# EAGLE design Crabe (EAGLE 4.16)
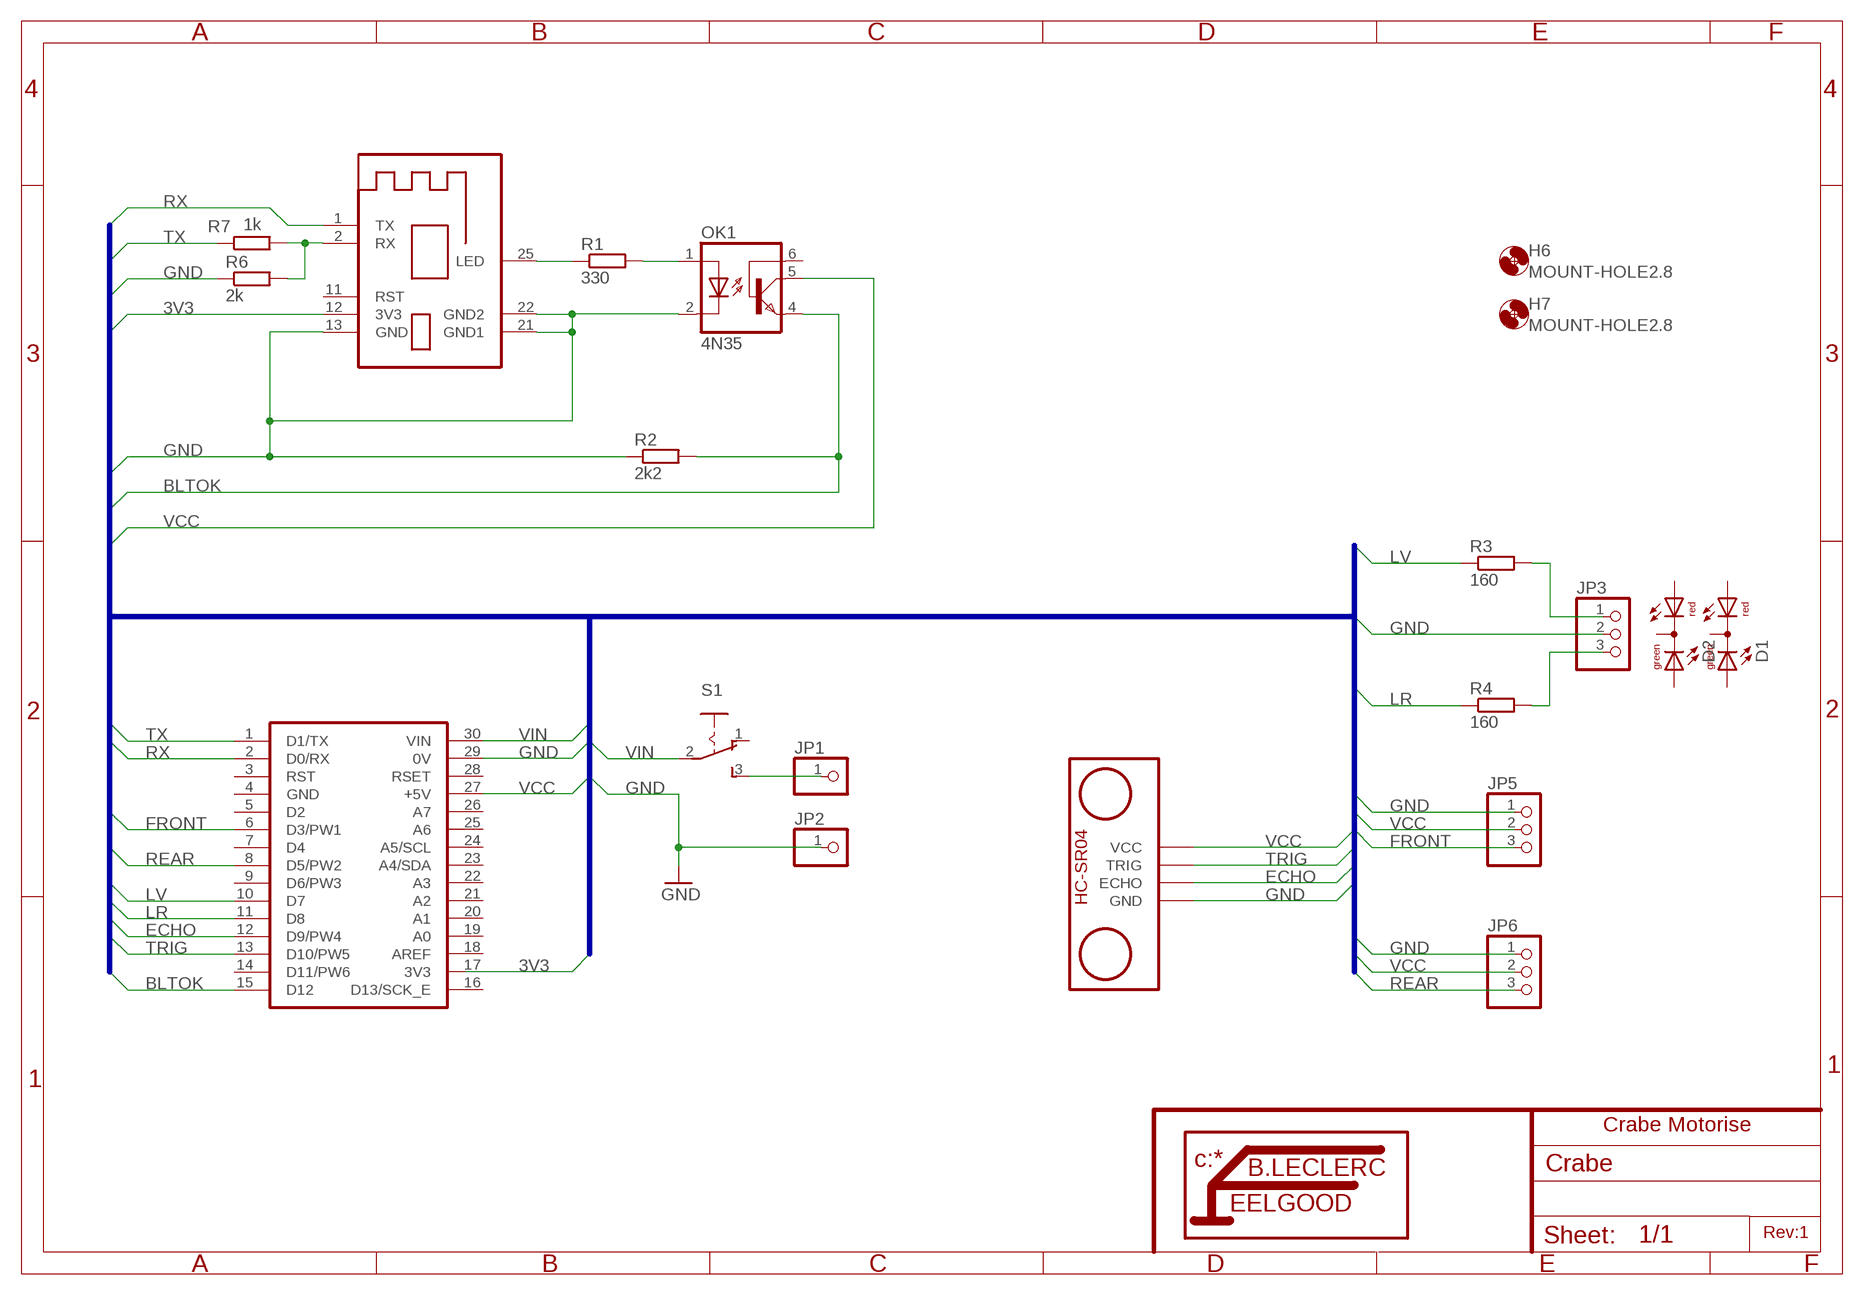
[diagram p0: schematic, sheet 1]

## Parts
BT1  SPP-BT  [SPP-BT]
D1  DUOLED5MM  [DUOLED5MM]
D2  DUOLED5MM  [DUOLED5MM]
H6  MOUNT-HOLE2.8  [2,8]
H7  MOUNT-HOLE2.8  [2,8]
JP1  PINHD-1X1  [1X01]
JP2  PINHD-1X1  [1X01]
JP3  PINHD-1X3  [1X03]
JP5  PINHD-1X3  [1X03]
JP6  PINHD-1X3  [1X03]
OK1  4N35  [DIL06]
R1  330  R-EU_M1206  [M1206]
R2  2k2  R-EU_M1206  [M1206]
R3  160  R-EU_M1206  [M1206]
R4  160  R-EU_M1206  [M1206]
R6  2k  R-EU_M1206  [M1206]
R7  1k  R-EU_M1206  [M1206]
S1  255SB  [255SB]
U1  NANO  [NANO]
U$3  HC-SR04  [HC-SR04]

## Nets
3V3: BT1.12(3V3)
BLTOK: OK1.4(EMI) R2.2 U1.15(D12)
ECHO: U1.12(D9/PW4) U$3.ECHO
FRONT: JP5.3 U1.6(D3/PW1)
GND: BT1.13(GND) BT1.21(GND1) BT1.22(GND2) JP2.1 JP3.2 JP5.1 JP6.1 OK1.2(C) R2.1 R6.1 U1.29(0V) U$3.GND
LR: R4.1 U1.11(D8)
LV: R3.1 U1.10(D7)
N$1: JP1.1 S1.3(S)
N$2: JP3.1 R3.2
N$3: JP3.3 R4.2
N$5: BT1.25(LED) R1.1
N$6: BT1.2(RX) R6.2 R7.2
N$7: OK1.1(A) R1.2
REAR: JP6.3 U1.8(D5/PW2)
RX: BT1.1(TX) U1.2(D0/RX)
TRIG: U1.13(D10/PW5) U$3.TRIG
TX: R7.1 U1.1(D1/TX)
VCC: JP5.2 JP6.2 OK1.5(COL) U1.27(+5V) U$3.VCC
VIN: S1.2(P) U1.30(VIN)
Unconnected: BT1.11(RST) D1.AG D1.AR D1.K(C) D2.AG D2.AR D2.K(C) OK1.6(BAS) S1.1(O) U1.3(RST) U1.5(D2) U1.7(D4) U1.9(D6/PW3) U1.14(D11/PW6) U1.16(D13/SCK_E) U1.18(AREF) U1.19(A0) U1.20(A1) U1.21(A2) U1.22(A3) U1.23(A4/SDA) U1.24(A5/SCL) U1.25(A6) U1.26(A7) U1.28(RSET)

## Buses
B$1

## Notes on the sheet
- Crabe Motorise
- Rev:1

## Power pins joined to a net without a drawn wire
3V3: U1.17(3V3)
GND: U1.4(GND)

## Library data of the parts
BT1 = Arduino:SPP-BT
D1 D2 = led:DUOLED5MM: DUO LED 2 colors, 5 mm, round
H6 H7 = holes:MOUNT-HOLE: MOUNTING HOLE with drill center marker
JP1 JP2 = pinhead:PINHD-1X1: PIN HEADER
JP3 JP5 JP6 = pinhead:PINHD-1X3: PIN HEADER
OK1 = optocoupler:4N35: MOTOROLA OPTO COUPLER
R1-R4 R6 R7 = rcl:R-EU_: RESISTOR, European symbol
S1 = switch:255SB: SLIDING SWITCH distributor Buerklin, 11G810
U1 = Arduino:NANO
U$3 = Arduino:HC-SR04

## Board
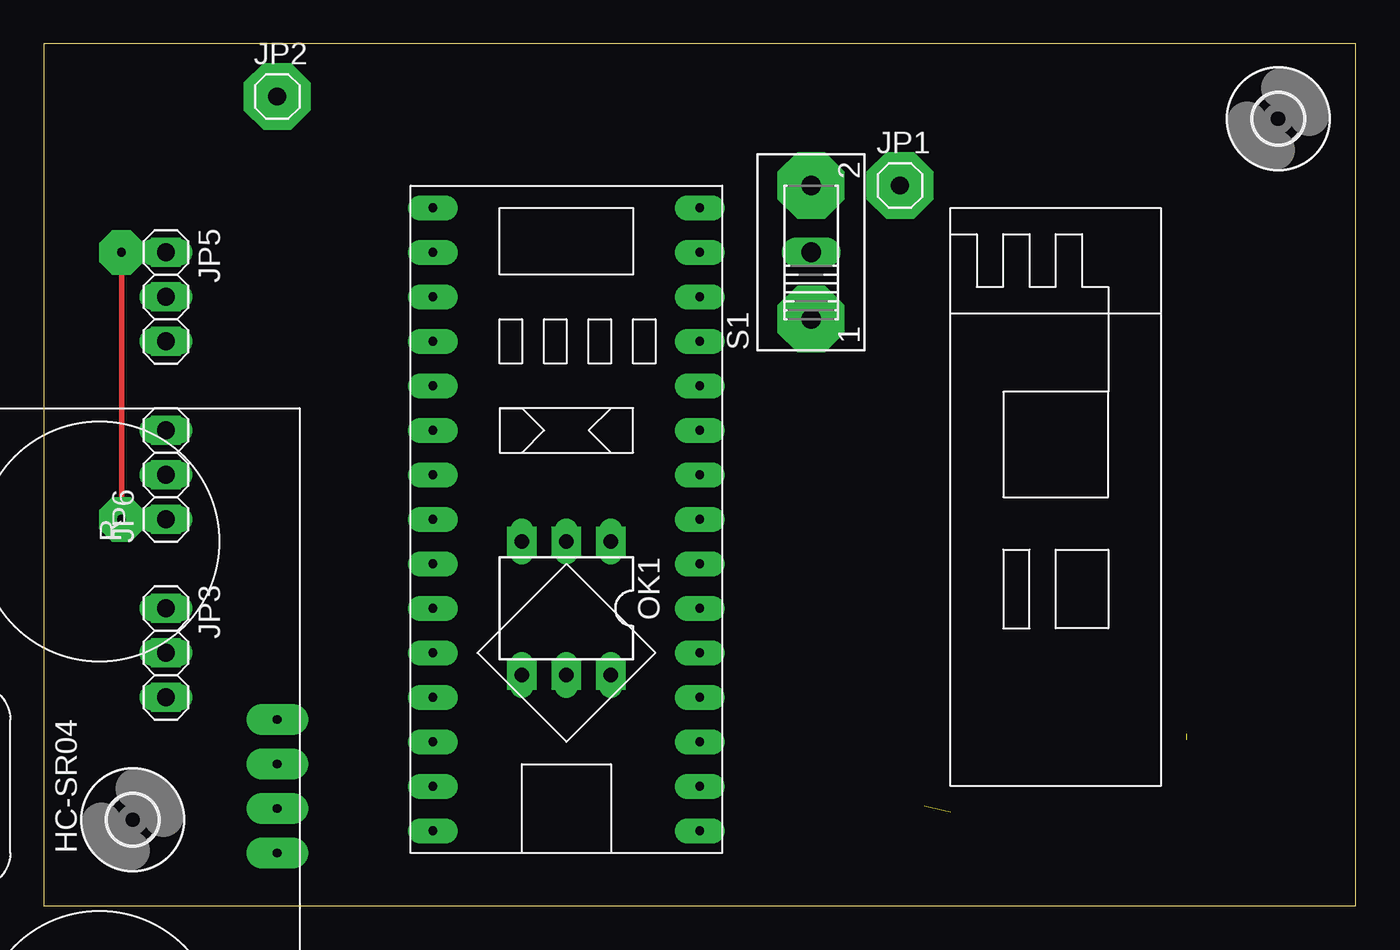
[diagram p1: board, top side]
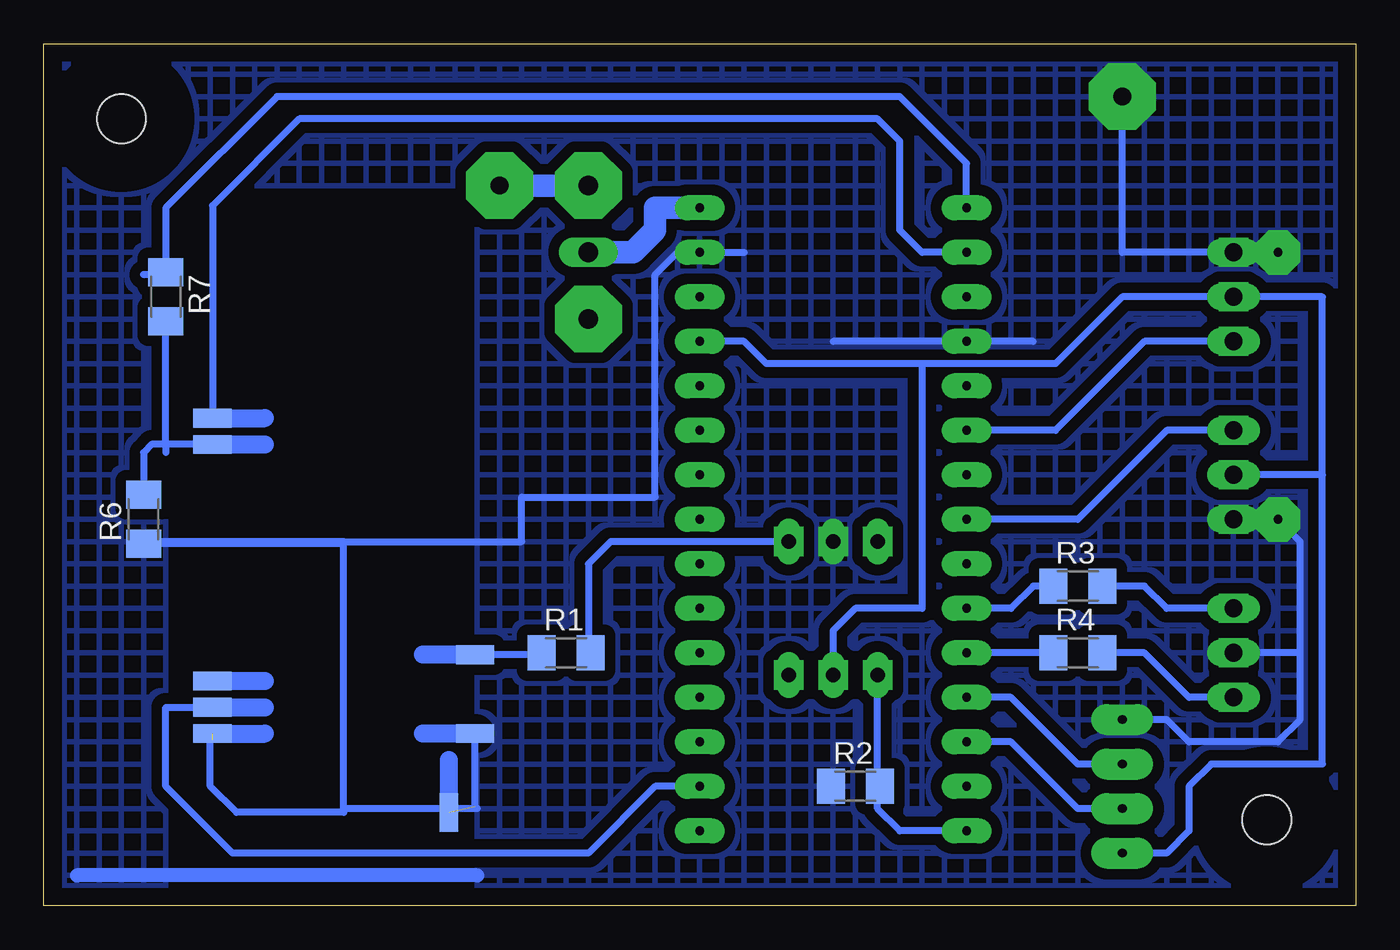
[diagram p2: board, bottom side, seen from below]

Size 74.91 x 49.2 mm. Coordinates in mm from the lower left corner, seen from the top.
Outline: 0,0 74.91,0 74.91,49.2 0,49.2 0,0
Copper layers (1*16): Top 0.035mm / dielectric 1.5mm / Bottom 0.035mm
Design rules "default": minimum track width 10mil, minimum drill 24mil, track to track 8mil, track to pad 8mil, pad to pad 8mil, via to via 8mil, smd to smd 8mil, copper to edge 40mil, drill to drill 8mil, minimum pad ring 10mil, minimum via ring 8mil, stop-mask expansion 4mil, vias tented up to drill 0mil, thermal gap 10mil

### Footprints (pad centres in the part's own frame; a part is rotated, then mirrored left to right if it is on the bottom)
SPP-BT = smd 2.184 x 1.067 bottom: 1 7.5,4.5; 2 7.5,3; 11 7.5,-10.5; 12 7.5,-12; 13 7.5,-13.5; 22 -7.5,-13.5; 25 -7.5,-9 | smd 1.067 x 2.184 bottom: 21 -6,-18
DUOLED5MM = drill 0.813 long: AG -2.54,0; AR 2.54,0; K 0,0
2,8 = hole 2.8: 0,0
1X01 = drill 1.016 octagon: 1 0,0
1X03 = drill 1.016 long: 1 -2.54,0; 2 0,0; 3 2.54,0
DIL06 = drill 0.813 long: 1 -2.54,-3.81; 2 0,-3.81; 3 2.54,-3.81; 4 2.54,3.81; 5 0,3.81; 6 -2.54,3.81
M1206 = smd 1.6 x 2: 1 -1.4,0; 2 1.4,0
255SB = drill 1.118 long: 1 -3.81,0; 2 0,0; 3 3.81,0
NANO = drill 0.5 pad 1.422 long: 1 -7.62,17.78; 2 -7.62,15.24; 3 -7.62,12.7; 4 -7.62,10.16; 5 -7.62,7.62; 6 -7.62,5.08; 7 -7.62,2.54; 8 -7.62,0; 9 -7.62,-2.54; 10 -7.62,-5.08; 11 -7.62,-7.62; 12 -7.62,-10.16; 13 -7.62,-12.7; 14 -7.62,-15.24; 15 -7.62,-17.78; 16 7.62,-17.78; 17 7.62,-15.24; 18 7.62,-12.7; 19 7.62,-10.16; 20 7.62,-7.62; 21 7.62,-5.08; 22 7.62,-2.54; 23 7.62,0; 24 7.62,2.54; 25 7.62,5.08; 26 7.62,7.62; 27 7.62,10.16; 28 7.62,12.7; 29 7.62,15.24; 30 7.62,17.78
HC-SR04 = drill 0.5 pad 1.778 long: ECHO 1.27,-10.16; GND 3.81,-10.16; TRIG -1.27,-10.16; VCC -3.81,-10.16

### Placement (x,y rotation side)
BT1  57.78,23.33 0 top
D1  not placed on the board
D2  not placed on the board
H6  5.08,4.92 0 top
H7  70.48,44.92 0 top
JP1  48.89,41.11 0 top
JP2  13.33,46.19 0 top
JP3  6.98,14.44 270 top
JP5  6.98,34.76 270 top
JP6  6.98,24.6 90 top
OK1  29.84,16.98 180 top
R1  45.08,14.44 0 bottom
R2  28.57,6.82 0 bottom
R3  15.87,18.25 0 bottom
R4  15.87,14.44 0 bottom
R6  69.21,22.06 90 bottom
R7  67.94,34.76 270 bottom
S1  43.81,37.3 90 top
U1  29.84,22.06 0 top
U$3  3.17,6.82 90 top

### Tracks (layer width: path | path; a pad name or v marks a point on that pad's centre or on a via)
3V3
  Bottom 0.406: BT1.12 67.94,11.33 67.94,6.82 64.13,3.01 43.81,3.01 40,6.82 U1.17
BLTOK
  Bottom 0.406: U1.15 26.03,4.28 27.3,5.55 27.3,6.82 | 27.3,6.82 R2.2 | 27.3,6.82 OK1.4
ECHO
  Bottom 0.406: U1.12 19.68,11.9 15.87,8.09 U$3.ECHO
FRONT
  Bottom 0.406: JP5.3 12.06,32.22 17.14,27.14 U1.6
GND  (via drill 0.5 pad 1.68, 0.5 pad 2.54, 0.5 pad 3.81)  (2 unrouted)
  Top 0.305: JP5.1 v4.44,37.3 v4.44,22.06
  Bottom 0.406: U$3.GND 10.79,10.63 9.52,9.36 4.44,9.36 3.17,10.63 3.17,14.44 | 3.17,14.44 JP3.2 | 3.17,14.44 3.17,20.79 v4.44,22.06 JP6.1 | JP5.1 13.33,37.3 JP2.1 | 18.41,32.22 U1.4 29.84,32.22 | 34.92,37.3 U1.29 38.73,37.3 40,36.03 40,23.33 47.62,23.33 47.62,20.79 57.78,20.79 | 65.28,9.48 65.4,9.36 65.4,6.82 63.91,5.33 57.78,5.33 57.78,5.55 | 57.78,20.79 69.21,20.79 R6.1 57.91,20.66 57.78,20.79 | 57.78,5.55 57.78,20.79 | BT1.22 50.28,5.67 50.16,5.55 57.78,5.55
  Bottom 0.813: 50.16,1.74 73.02,1.74
  other vias: 13.33,46.19 29.84,20.79 6.98,14.44 6.98,22.06 6.98,37.3
  pour Bottom (isolate 0.61, no thermals, hatched): 0.63,48.73 74.29,48.73 74.29,0.47 67.94,0.47 67.94,41.11 50.16,41.11 50.16,0.47 0.63,0.47
LR
  Bottom 0.406: 17.14,14.44 R4.1 U1.11
LV
  Bottom 0.406: U1.10 19.68,16.98 18.41,18.25 R3.1 17.14,18.25
N$1
  Bottom 1.27: S1.3 JP1.1
N$2
  Bottom 0.406: R3.2 12.06,18.25 10.79,16.98 JP3.1
N$3
  Bottom 0.406: R4.2 12.06,14.44 9.52,11.9 JP3.3
N$4  (via drill 0.5 pad 3.81)
  other vias: 48.89,41.11
N$5
  Bottom 0.406: R1.1 46.35,14.44 46.46,14.33 BT1.25
N$6
  Bottom 0.406: BT1.2 67.94,26.33 | 67.94,26.33 68.75,26.33 69.21,25.87 R6.2 69.21,23.33 | 67.94,26.33 67.94,25.87 | 67.94,26.33 R7.2
N$7
  Bottom 0.406: OK1.1 42.54,20.79 43.81,19.52 43.81,14.44 R1.2
N$8  (via drill 0.5 pad 3.81)
  other vias: 43.81,41.11
N$9  (via drill 0.5 pad 3.81)
  other vias: 43.81,33.49
N$10  (via drill 0.5 pad 1.68)
  other vias: 27.3,13.17
N$11  (via drill 0.5 pad 1.68)
  other vias: 29.84,13.17
N$12  (via drill 0.5 pad 1.68)
  other vias: 32.38,13.17
N$13  (via drill 0.5 pad 1.68)
  other vias: 32.38,20.79
N$15  (via drill 0.5 pad 1.68)
  other vias: 27.3,20.79
N$19  (via drill 0.5 pad 1.68)
  other vias: 6.98,34.76
N$20  (via drill 0.5 pad 1.68)
  other vias: 6.98,32.22
N$21  (via drill 0.5 pad 1.68)
  other vias: 6.98,27.14
N$22  (via drill 0.5 pad 1.68)
  other vias: 6.98,24.6
N$23  (via drill 0.5 pad 1.68)
  other vias: 6.98,16.98
N$24  (via drill 0.5 pad 1.68)
  other vias: 6.98,14.44
N$25  (via drill 0.5 pad 1.68)
  other vias: 6.98,11.9
N$26  (via drill 0.5 pad 1.68)
  other vias: 43.81,37.3
REAR
  Bottom 0.406: JP6.3 10.79,27.14 15.87,22.06 U1.8
RX
  Bottom 0.406: BT1.1 65.28,39.96 60.32,44.92 27.3,44.92 26.03,43.65 26.03,38.57 24.76,37.3 U1.2
TRIG
  Bottom 0.406: U1.13 19.68,9.36 15.87,5.55 U$3.TRIG
TX
  Bottom 0.406: U1.1 22.22,42.38 26.03,46.19 61.59,46.19 67.94,39.84 67.94,36.03 69.21,36.03 R7.1
VCC
  Bottom 0.406: U$3.VCC 10.79,3.01 9.52,4.28 9.52,6.82 8.25,8.09 1.9,8.09 1.9,24.6 | 1.9,24.6 1.9,34.76 JP5.2 13.33,34.76 17.14,30.95 24.76,30.95 | 1.9,24.6 JP6.2 | 24.76,30.95 33.65,30.95 34.92,32.22 U1.27 | OK1.5 29.84,15.71 28.57,16.98 24.76,16.98 24.76,30.95
VIN
  Bottom 1.27: U1.30 40,39.84 40,38.57 41.27,37.3 S1.2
